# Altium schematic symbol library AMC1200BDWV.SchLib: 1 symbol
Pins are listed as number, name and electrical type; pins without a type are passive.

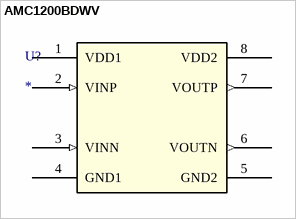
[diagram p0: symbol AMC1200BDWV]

## AMC1200BDWV
designator U?
No Description Available; Mfr_Name: Texas Instruments
footprint DWV8_TEX
pins: 1 VDD1 (power), 2 VINP (in), 3 VINN (in), 4 GND1 (power), 5 GND2 (power), 6 VOUTN (out), 7 VOUTP (out), 8 VDD2 (power)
